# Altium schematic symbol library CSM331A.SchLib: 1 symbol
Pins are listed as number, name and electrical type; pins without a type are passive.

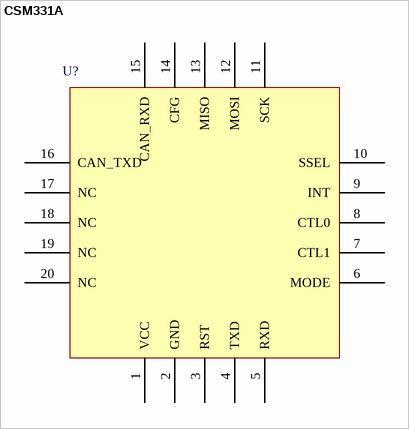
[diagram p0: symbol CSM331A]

## CSM331A
designator U?
footprint CSM331A
pins: 1 VCC, 2 GND, 3 RST, 4 TXD, 5 RXD, 6 MODE, 7 CTL1, 8 CTL0, 9 INT, 10 SSEL, 11 SCK, 12 MOSI, 13 MISO, 14 CFG, 15 CAN_RXD, 16 CAN_TXD, 17 NC, 18 NC, 19 NC, 20 NC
